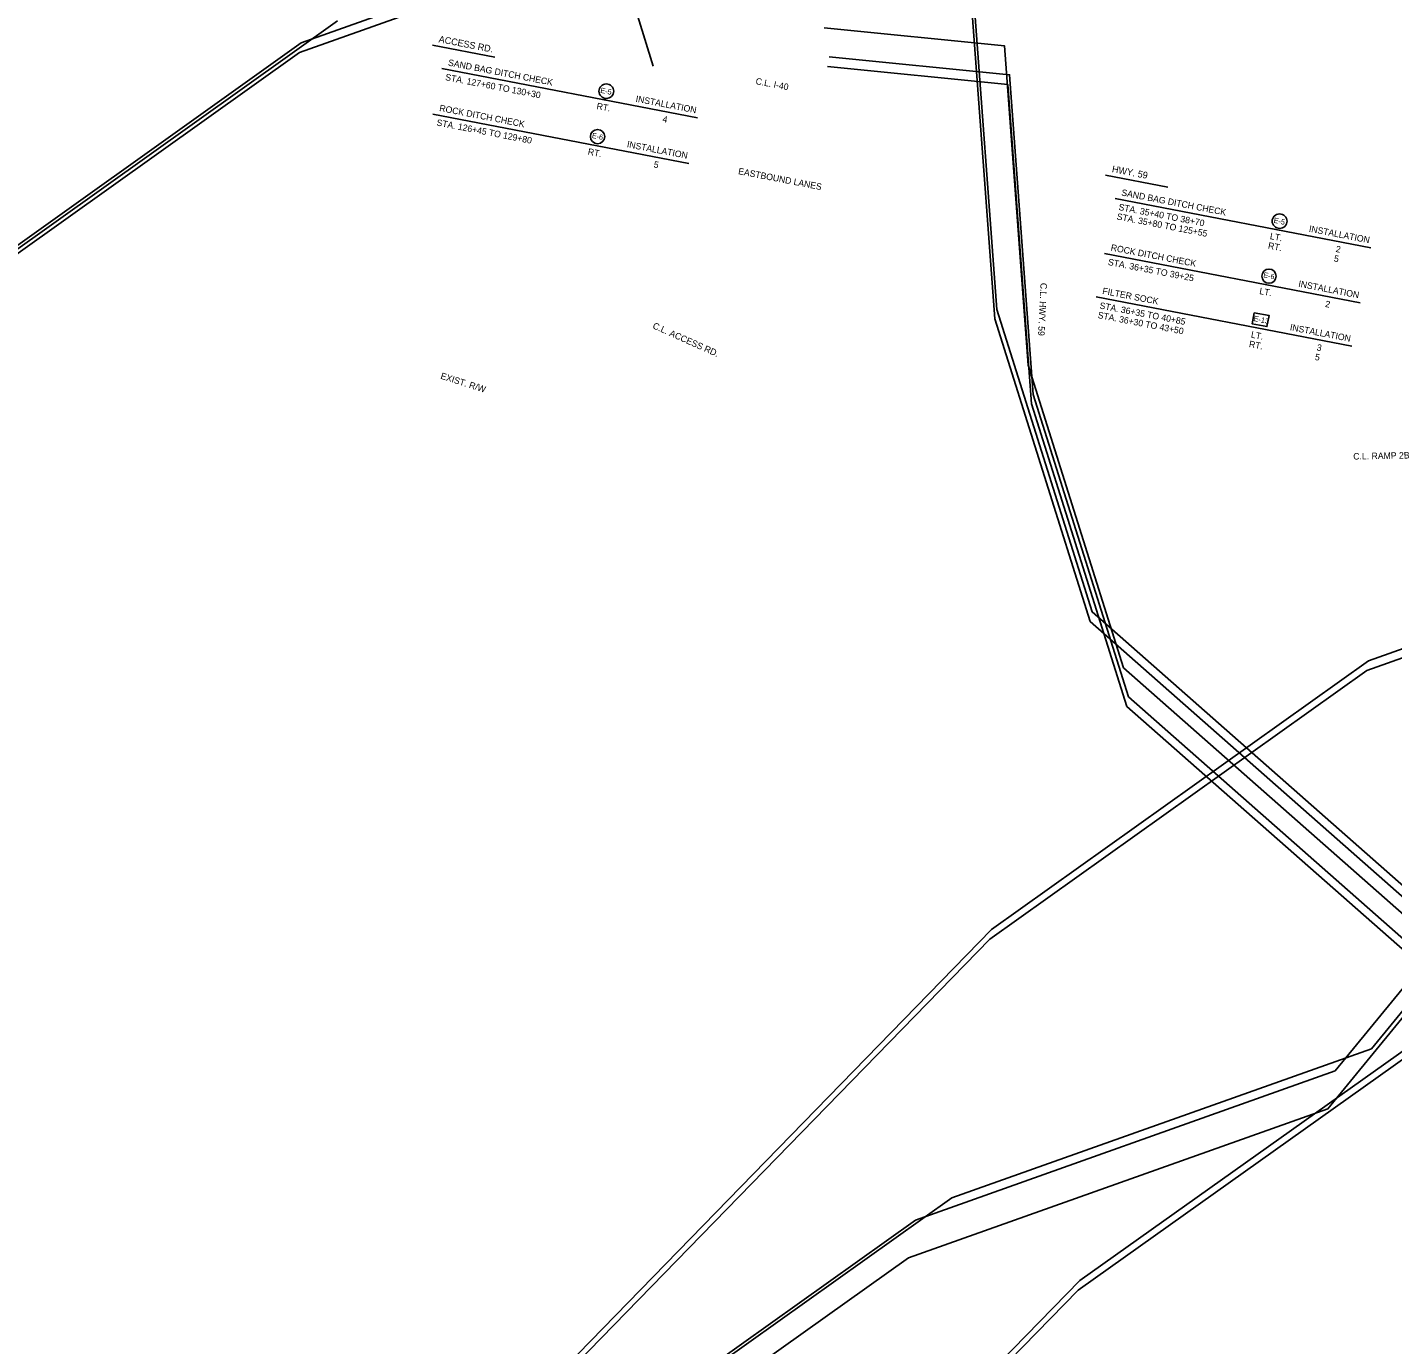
# Model space of a CAD drawing. Extents: x 605579 to 613541, y 415511 to 420599.
# Drawn here: x 609780 to 611043, y 418408 to 419627 of the extents above; entities that cross this region are included whole.
import ezdxf

# ---------------------------------------------------------------- set-up
doc = ezdxf.new("R2010")
doc.units = 0
for name, color, linetype in [('Default', 7, 'Continuous'), ('R_Bench', 7, 'Continuous'), ('R_Draft', 7, 'Continuous'), ('R_Shld', 7, 'Continuous'), ('R_Slope Break', 7, 'Continuous'), ('R_Subgrade', 7, 'Continuous')]:
    doc.layers.add(name, color=color, linetype=linetype)

msp = doc.modelspace()

# ---------------------------------------------------------------- linework, layer by layer
at = {"layer": 'R_Bench'}
for p, q in [((610154.4, 419610.9), (610212.1, 419599.8)), ((610163.2, 419589.3), (610399.8, 419543.6)), ((610155, 419547.2), (610391.7, 419501.5)), ((610777.5, 419490.7), (610835.2, 419479.5)), ((610786.2, 419469), (611022.9, 419423.3)), ((610776.4, 419418.2), (611013.1, 419372.5)), ((610768.7, 419377.9), (611005.3, 419332.2))]:
    msp.add_line(p, q, dxfattribs=at)
at = {"layer": 'R_Draft'}
for points in [[(610607.3, 419977.9), (610421.2, 419750.9), (610033, 419613)], [(610605.7, 419969.1), (610419.6, 419742), (610031.4, 419604.1)], [(610488, 419678.5), (610654.8, 419662.1), (610676.8, 419366.3)], [(610358.7, 419591.5), (610344.5, 419637.5), (610230, 419659.6)], [(610486.3, 419669.7), (610653.1, 419653.2), (610675, 419357.5)], [(610066.7, 419633.4), (609717.8, 419384.7), (608824.5, 418467.8)], [(610517, 419626.9), (610683.9, 419610.4), (610705.8, 419314.7)], [(610033, 419613), (609684, 419364.2), (608790.8, 418447.3)], [(610031.4, 419604.1), (609682.5, 419355.4), (608789.2, 418438.4)], [(610521.7, 419600), (610688.6, 419583.5), (610710.5, 419287.7)], [(610520, 419591.1), (610686.9, 419574.6), (610708.8, 419278.9)], [(611593.5, 419397.2), (611407.5, 419170.1), (611019.3, 419032.1)], [(611595.1, 419406.1), (611409.1, 419179), (611020.9, 419041)], [(610675, 419357.5), (610763.3, 419077.5), (611072.3, 418805.1)], [(610676.8, 419366.3), (610765, 419086.3), (611074, 418813.9)], [(610705.8, 419314.7), (610794, 419034.7), (611103, 418762.2)], [(610710.5, 419287.7), (610798.7, 419007.8), (611107.8, 418735.3)], [(610708.8, 419278.9), (610797, 418998.9), (611106.1, 418726.5)], [(611020.9, 419041), (610672, 418792.2), (609778.9, 417875.2)], [(611019.3, 419032.1), (610670.4, 418783.4), (609777.3, 417866.3)], [(611209.5, 418908.9), (611023.5, 418681.8), (610635.3, 418543.9)], [(611175.8, 418888.4), (610989.8, 418661.4), (610601.6, 418523.4)], [(611169.2, 418853.4), (610983.2, 418626.3), (610595, 418488.4)], [(611102.9, 418715.6), (610753.7, 418467.3), (609859.5, 417551.2)], [(611101.3, 418706.8), (610752.1, 418458.4), (609857.9, 417542.3)], [(610635.3, 418543.9), (610286.3, 418295.2), (609393, 417378.2)], [(610601.6, 418523.4), (610252.6, 418274.7), (609359.3, 417357.8)], [(610595, 418488.4), (610246, 418239.7), (609352.7, 417322.8)]]:
    msp.add_lwpolyline(points, dxfattribs=at)
at = {"layer": 'R_Shld'}
for centre in [(610307.3, 419526.3), (610928.7, 419397.1)]:
    msp.add_circle(centre, 6.61, dxfattribs=at)
at = {"layer": 'R_Slope Break'}
msp.add_lwpolyline([(610915, 419363.3), (610928.8, 419360.7), (610926.8, 419350.4), (610913.1, 419353)], close=True, dxfattribs=at)
for centre in [(610315.4, 419568.3), (610938.5, 419448)]:
    msp.add_ellipse(centre, major_axis=(-6.76, 1.31), ratio=0.97521, dxfattribs=at)

# ---------------------------------------------------------------- texts
at = {"layer": 'Default'}
for s, rotation, p in [('C.L. HWY. 59', 267.2385, (610717.3, 419391)), ('C.L. ACCESS RD.', 335.8864, (610357.7, 419349.1)), ('C.L. RAMP 2B', 1.1692, (611006.7, 419227.3))]:
    msp.add_text(s, height=6, rotation=rotation, dxfattribs=at).set_placement(p)
at = {"layer": 'R_Bench'}
for s, height, p in [('ACCESS RD.', 6.25, (610159.9, 419613.7)), ('SAND BAG DITCH CHECK', 6, (610168.6, 419592.1)), ('STA. 127+60 TO 130+30', 6, (610166, 419578.6)), ('INSTALLATION', 6, (610342.2, 419558.6)), ('ROCK DITCH CHECK', 6, (610160.5, 419550)), ('RT.', 6, (610306, 419551.8)), ('4', 6, (610367, 419539.8)), ('STA. 126+45 TO 129+80', 6, (610157.9, 419536.6)), ('INSTALLATION', 6, (610334.1, 419516.5)), ('RT.', 6, (610297.9, 419509.7)), ('5', 6, (610358.9, 419497.8)), ('HWY. 59', 6.25, (610783, 419493.5)), ('SAND BAG DITCH CHECK', 6, (610791.7, 419471.8)), ('STA. 35+40 TO 38+70', 6, (610789.1, 419458.4)), ('STA. 35+80 TO 125+55', 6, (610787.4, 419449.6)), ('LT.', 6, (610929.2, 419431.5)), ('INSTALLATION', 6, (610965.3, 419438.3)), ('ROCK DITCH CHECK', 6, (610781.9, 419420.9)), ('RT.', 6, (610927.4, 419422.7)), ('2', 6, (610990.1, 419419.6)), ('STA. 36+35 TO 39+25  ', 6, (610779.3, 419407.5)), ('5', 6, (610988.4, 419410.8)), ('FILTER SOCK', 6, (610774.1, 419380.7)), ('LT.', 6, (610919.4, 419380.6)), ('INSTALLATION', 6, (610955.5, 419387.4)), ('STA. 36+35 TO 40+85', 6, (610771.5, 419367.2)), ('2', 6, (610980.3, 419368.7)), ('STA. 36+30 TO 43+50', 6, (610769.8, 419358.4)), ('LT.', 6, (610911.6, 419340.3)), ('INSTALLATION', 6, (610947.7, 419347.1)), ('RT.', 6, (610909.8, 419331.6)), ('3', 6, (610972.5, 419328.4)), ('5', 6, (610970.8, 419319.6))]:
    msp.add_text(s, height=height, rotation=349.0745, dxfattribs=at).set_placement(p)
at = {"layer": 'R_Draft'}
for s, p in [('C.L. I-40', (610453.2, 419574.9)), ('EASTBOUND LANES', (610437.1, 419491.6))]:
    msp.add_text(s, height=6, rotation=349.0745, dxfattribs=at).set_placement(p)
at = {"layer": 'R_Shld'}
for p in [(610301.8, 419525.1), (610923.2, 419396.1)]:
    msp.add_text('E-6 ', height=4.8, rotation=349.0745, dxfattribs=at).set_placement(p)
at = {"layer": 'R_Slope Break'}
for s, height, rotation, p in [('E-5', 4.88, 349.0745, (610309.6, 419566.9)), ('E-5', 4.88, 349.0745, (610932.7, 419446.6)), ('E-13', 5, 348.6922, (610914, 419355.7))]:
    msp.add_text(s, height=height, rotation=rotation, dxfattribs=at).set_placement(p)
at = {"layer": 'R_Subgrade'}
msp.add_text('EXIST. R/W', height=6, rotation=342.2779, dxfattribs=at).set_placement((610161.5, 419302.3))

doc.saveas('drawing.dxf')
